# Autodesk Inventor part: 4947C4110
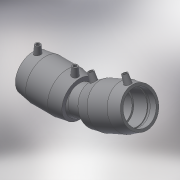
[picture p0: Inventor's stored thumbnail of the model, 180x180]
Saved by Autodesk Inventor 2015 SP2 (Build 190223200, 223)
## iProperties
Created: 2017-06
Part Number: 4947C4110
Material: Generic
Description: PLASSON ADJUSTABLE ELBOW 110
Document SubType Name: Modeling
Designer: KIM
Mass: 55.0731 g
Surface Area: 148.067 cm^2
Volume: 55.0731 cm^3
Density: 1 g/cm^3
Appearance: Default
Author: KIM
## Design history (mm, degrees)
derived "4947C4.ipt"
feature "Solid1::4947C4.ipt"
tag "TaggingFeature1"
body "Solid1"
other parameters: "d0" = 144.8, "d5" = 126, "d8" = 168 deg, "d10" = 32, "d11" = 10.66667, "d29" = 83, "d30" = 15, "d31" = 57.92, "d34" = 5 deg, "d41" = 4, "d42" = 14, "d43" = 0, "d48" = 99, "d49" = 24 deg, "d50" = 362, "d51" = 78 deg, "d52" = 90 deg, "d55" = 32.4, "d57" = 168 deg, "d58" = 6.48, "d60" = 40.94964, "d62" = 3, "d63" = 0, "L_" = 362, "A_" = 83, "d_2" = 12, "L_0" = 148, "d54" = 64.8, "d59" = 136.4988
